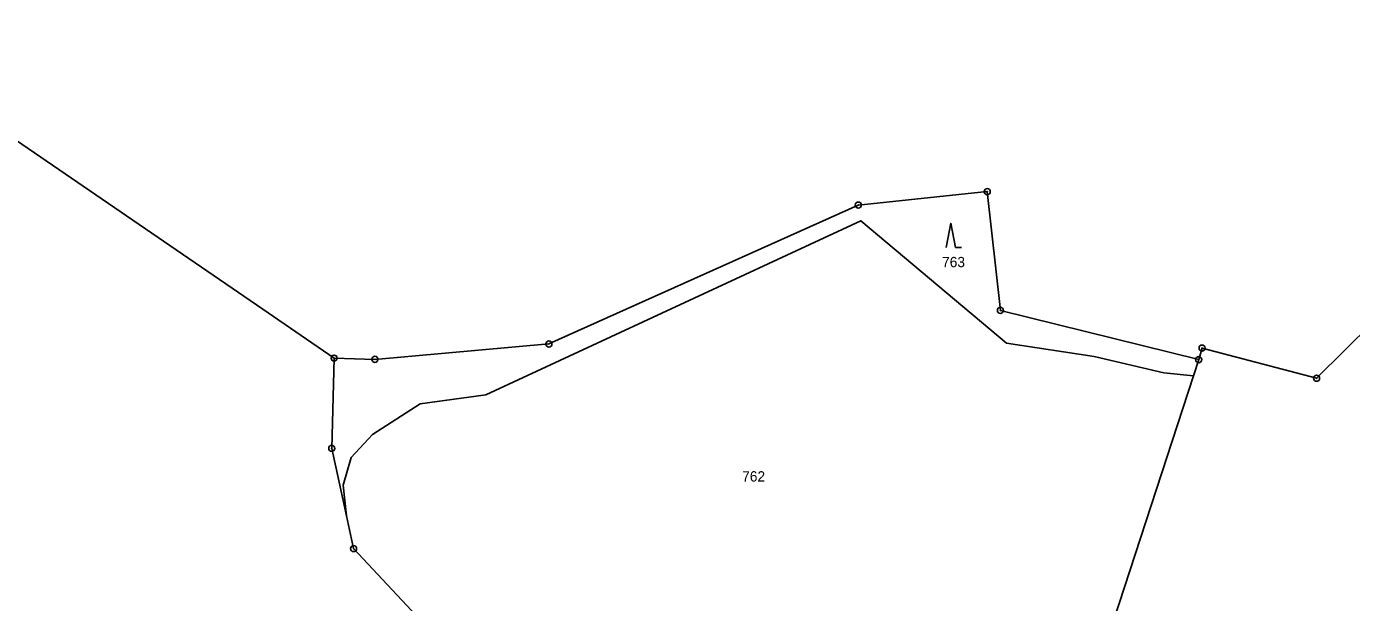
# Model space of a CAD drawing. Extents: x -754445 to -751443, y -1030748 to -1028224.
# Drawn here: x -753097.8 to -752878.6, y -1029236.8 to -1029141.6 of the extents above; entities that cross this region are included whole.
import ezdxf
from ezdxf.enums import TextEntityAlignment as Align

# ---------------------------------------------------------------- set-up
doc = ezdxf.new("R2010")
doc.units = 0
doc.header["$LTSCALE"] = 0.68
for name, color, linetype, lineweight in [('1', 7, 'Continuous', 25), ('3', 7, 'Continuous', 25), ('8', 7, 'Continuous', 25)]:
    doc.layers.add(name, color=color, linetype=linetype, lineweight=lineweight)
doc.layers.add('2', color=7, linetype='Continuous')

msp = doc.modelspace()

# ---------------------------------------------------------------- linework, layer by layer
at = {"layer": '1'}
msp.add_line((-753040.15, -1029196.65), (-753046.89, -1029196.45), dxfattribs=at)
for points in [[(-753058.69, -1029188.38), (-753111.89, -1029152.01), (-753148.53, -1029141.63)], [(-752938.85, -1029168.92), (-752960.19, -1029171.14), (-753011.36, -1029194.11), (-753040.15, -1029196.65)], [(-752903.88, -1029196.7), (-752936.67, -1029188.55), (-752938.85, -1029168.92)], [(-752904.75, -1029199.37), (-752909.62, -1029198.86), (-752921.18, -1029196.17), (-752935.67, -1029193.96), (-752959.78, -1029173.74), (-753021.77, -1029202.52), (-753032.65, -1029203.99), (-753040.54, -1029209.09), (-753044.05, -1029212.88), (-753045.42, -1029217.44), (-753044.85, -1029222.5)], [(-753044.85, -1029222.5), (-753047.28, -1029211.38), (-753046.89, -1029196.45), (-753058.69, -1029188.38)], [(-752875.15, -1029190.6), (-752884.37, -1029199.78), (-752903.32, -1029194.79)], [(-752903.32, -1029194.79), (-752903.88, -1029196.7), (-752904.75, -1029199.37), (-752923.17, -1029255.77)], [(-753026.04, -1029244.41), (-753028.48, -1029244.15), (-753043.67, -1029227.93), (-753044.85, -1029222.5)]]:
    msp.add_lwpolyline(points, dxfattribs=at)
at = {"layer": '3'}
msp.add_line((-752944.13, -1029178.16), (-752943.134, -1029178.16), dxfattribs=at)
msp.add_lwpolyline([(-752944.13, -1029178.16), (-752944.88, -1029174.16), (-752945.63, -1029178.16)], dxfattribs=at)
at = {"layer": '8'}
for centre, radius in [((-752938.85, -1029168.9199), 0.5), ((-752938.85, -1029168.9199), 0.0303), ((-752960.19, -1029171.1399), 0.5), ((-752960.19, -1029171.1399), 0.0303), ((-752936.67, -1029188.5499), 0.5), ((-752936.67, -1029188.5499), 0.0303), ((-753011.36, -1029194.1099), 0.5), ((-753011.36, -1029194.1099), 0.0303), ((-752903.32, -1029194.7899), 0.5), ((-753046.89, -1029196.4499), 0.5), ((-753046.89, -1029196.4499), 0.0303), ((-753040.15, -1029196.6499), 0.5), ((-752903.88, -1029196.6999), 0.5), ((-752903.32, -1029194.7899), 0.0303), ((-753040.15, -1029196.6499), 0.0303), ((-752903.88, -1029196.6999), 0.0303), ((-752884.37, -1029199.7799), 0.5), ((-752884.37, -1029199.7799), 0.0303), ((-753047.28, -1029211.3799), 0.5), ((-753047.28, -1029211.3799), 0.0303), ((-753043.67, -1029227.9299), 0.5), ((-753043.67, -1029227.9299), 0.0303)]:
    msp.add_circle(centre, radius, dxfattribs=at)

# ---------------------------------------------------------------- texts
at = {"layer": '2'}
for s, p in [('763', (-752944.429, -1029181.416)), ('762', (-752977.499, -1029216.846))]:
    msp.add_text(s, height=1.7, dxfattribs=at).set_placement(p, align=Align.CENTER)

doc.saveas('drawing.dxf')
